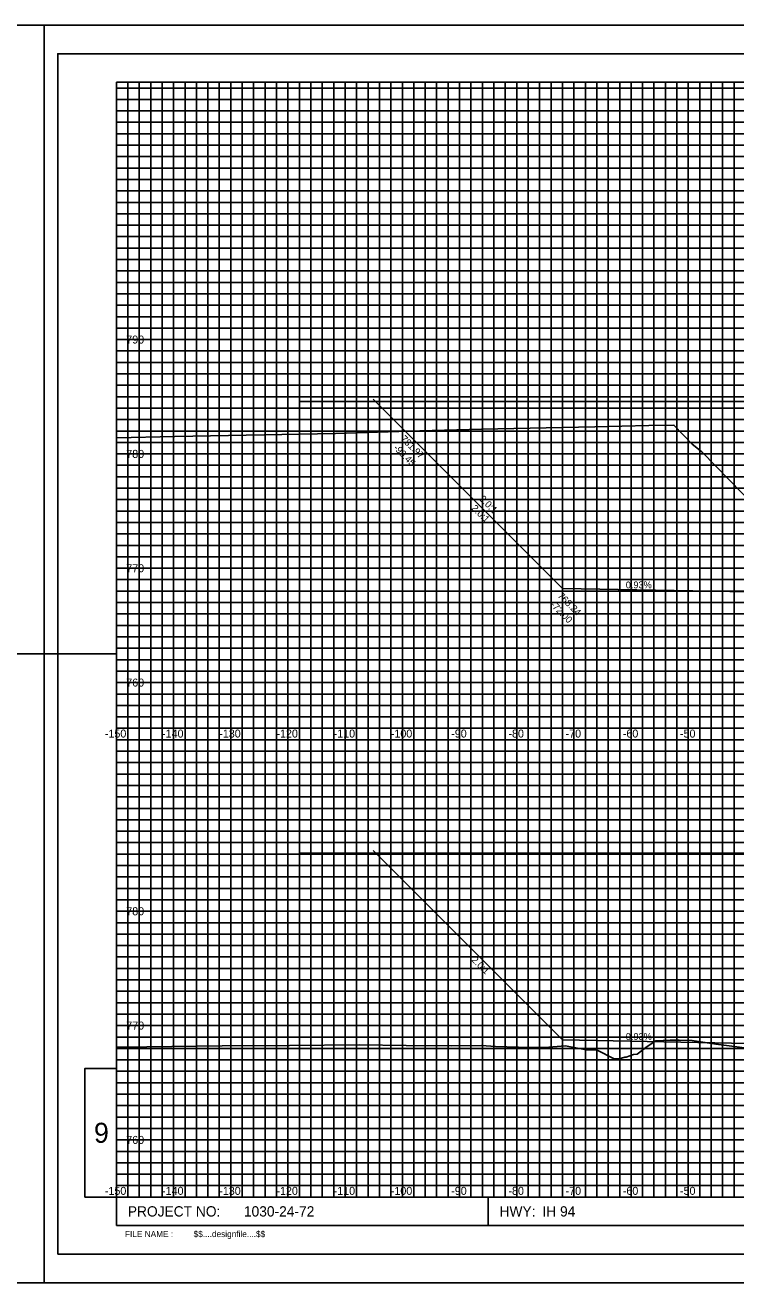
# Model space of a CAD drawing. Extents: x 578243 to 601557, y 174899 to 175559.
# Drawn here: x 600533.9 to 600658.2, y 175338.8 to 175558.8 of the extents above; entities that cross this region are included whole.
import ezdxf

# ---------------------------------------------------------------- set-up
doc = ezdxf.new("R2010")
doc.units = 0
for name, color, linetype in [('E_PROF_Grid', 7, 'Continuous'), ('E_PROF_GridMin', 7, 'Continuous'), ('P_CRDR_Label', 7, 'Continuous'), ('P_CRDR_Link', 7, 'Continuous'), ('P_E_XS_Ground', 7, 'Continuous'), ('P_RW_SlopeIntercepts', 7, 'Continuous'), ('P_XS_Text', 7, 'Continuous'), ('PLT_Sheet_Border', 7, 'Continuous'), ('PLT_Sheet_Info', 7, 'Continuous')]:
    doc.layers.add(name, color=color, linetype=linetype)

msp = doc.modelspace()

# ---------------------------------------------------------------- linework, layer by layer
at = {"layer": 'E_PROF_Grid'}
for p, q in [((600559.84, 175353.8), (600559.84, 175548.8)), ((600569.84, 175353.8), (600569.84, 175548.8)), ((600579.84, 175353.8), (600579.84, 175548.8)), ((600589.84, 175353.8), (600589.84, 175548.8)), ((600599.84, 175353.8), (600599.84, 175548.8)), ((600609.84, 175353.8), (600609.84, 175548.8)), ((600619.84, 175353.8), (600619.84, 175548.8)), ((600629.84, 175353.8), (600629.84, 175548.8)), ((600639.84, 175353.8), (600639.84, 175548.8)), ((600649.84, 175353.8), (600649.84, 175548.8)), ((600549.84, 175543.8), (600864.84, 175543.8)), ((600549.84, 175533.8), (600864.84, 175533.8)), ((600549.84, 175523.8), (600864.84, 175523.8)), ((600549.84, 175513.8), (600864.84, 175513.8)), ((600549.84, 175503.8), (600864.84, 175503.8)), ((600549.84, 175493.8), (600864.84, 175493.8)), ((600549.84, 175483.8), (600864.84, 175483.8)), ((600549.84, 175473.8), (600864.84, 175473.8)), ((600549.84, 175463.8), (600864.84, 175463.8)), ((600549.84, 175453.8), (600864.84, 175453.8)), ((600549.84, 175443.8), (600864.84, 175443.8)), ((600549.84, 175433.8), (600864.84, 175433.8)), ((600549.84, 175423.8), (600864.84, 175423.8)), ((600549.84, 175413.8), (600864.84, 175413.8)), ((600549.84, 175403.8), (600864.84, 175403.8)), ((600549.84, 175393.8), (600864.84, 175393.8)), ((600549.84, 175383.8), (600864.84, 175383.8)), ((600549.84, 175373.8), (600864.84, 175373.8)), ((600549.84, 175363.8), (600864.84, 175363.8))]:
    msp.add_line(p, q, dxfattribs=at)
at = {"layer": 'E_PROF_GridMin'}
for p, q in [((600549.84, 175547.8), (600864.84, 175547.8)), ((600551.84, 175353.8), (600551.84, 175548.8)), ((600553.84, 175353.8), (600553.84, 175548.8)), ((600555.84, 175353.8), (600555.84, 175548.8)), ((600557.84, 175353.8), (600557.84, 175548.8)), ((600561.84, 175353.8), (600561.84, 175548.8)), ((600563.84, 175353.8), (600563.84, 175548.8)), ((600565.84, 175353.8), (600565.84, 175548.8)), ((600567.84, 175353.8), (600567.84, 175548.8)), ((600571.84, 175353.8), (600571.84, 175548.8)), ((600573.84, 175353.8), (600573.84, 175548.8)), ((600575.84, 175353.8), (600575.84, 175548.8)), ((600577.84, 175353.8), (600577.84, 175548.8)), ((600581.84, 175353.8), (600581.84, 175548.8)), ((600583.84, 175353.8), (600583.84, 175548.8)), ((600585.84, 175353.8), (600585.84, 175548.8)), ((600587.84, 175353.8), (600587.84, 175548.8)), ((600591.84, 175353.8), (600591.84, 175548.8)), ((600593.84, 175353.8), (600593.84, 175548.8)), ((600595.84, 175353.8), (600595.84, 175548.8)), ((600597.84, 175353.8), (600597.84, 175548.8)), ((600601.84, 175353.8), (600601.84, 175548.8)), ((600603.84, 175353.8), (600603.84, 175548.8)), ((600605.84, 175353.8), (600605.84, 175548.8)), ((600607.84, 175353.8), (600607.84, 175548.8)), ((600611.84, 175353.8), (600611.84, 175548.8)), ((600613.84, 175353.8), (600613.84, 175548.8)), ((600615.84, 175353.8), (600615.84, 175548.8)), ((600617.84, 175353.8), (600617.84, 175548.8)), ((600621.84, 175353.8), (600621.84, 175548.8)), ((600623.84, 175353.8), (600623.84, 175548.8)), ((600625.84, 175353.8), (600625.84, 175548.8)), ((600627.84, 175353.8), (600627.84, 175548.8)), ((600631.84, 175353.8), (600631.84, 175548.8)), ((600633.84, 175353.8), (600633.84, 175548.8)), ((600635.84, 175353.8), (600635.84, 175548.8)), ((600637.84, 175353.8), (600637.84, 175548.8)), ((600641.84, 175353.8), (600641.84, 175548.8)), ((600643.84, 175353.8), (600643.84, 175548.8)), ((600645.84, 175353.8), (600645.84, 175548.8)), ((600647.84, 175353.8), (600647.84, 175548.8)), ((600651.84, 175353.8), (600651.84, 175548.8)), ((600653.84, 175353.8), (600653.84, 175548.8)), ((600655.84, 175353.8), (600655.84, 175548.8)), ((600657.84, 175353.8), (600657.84, 175548.8)), ((600549.84, 175545.8), (600864.84, 175545.8)), ((600549.84, 175541.8), (600864.84, 175541.8)), ((600549.84, 175539.8), (600864.84, 175539.8)), ((600549.84, 175537.8), (600864.84, 175537.8)), ((600549.84, 175535.8), (600864.84, 175535.8)), ((600549.84, 175531.8), (600864.84, 175531.8)), ((600549.84, 175529.8), (600864.84, 175529.8)), ((600549.84, 175527.8), (600864.84, 175527.8)), ((600549.84, 175525.8), (600864.84, 175525.8)), ((600549.84, 175521.8), (600864.84, 175521.8)), ((600549.84, 175519.8), (600864.84, 175519.8)), ((600549.84, 175517.8), (600864.84, 175517.8)), ((600549.84, 175515.8), (600864.84, 175515.8)), ((600549.84, 175511.8), (600864.84, 175511.8)), ((600549.84, 175509.8), (600864.84, 175509.8)), ((600549.84, 175507.8), (600864.84, 175507.8)), ((600549.84, 175505.8), (600864.84, 175505.8)), ((600549.84, 175501.8), (600864.84, 175501.8)), ((600549.84, 175499.8), (600864.84, 175499.8)), ((600549.84, 175497.8), (600864.84, 175497.8)), ((600549.84, 175495.8), (600864.84, 175495.8)), ((600549.84, 175491.8), (600864.84, 175491.8)), ((600549.84, 175489.8), (600864.84, 175489.8)), ((600549.84, 175487.8), (600864.84, 175487.8)), ((600549.84, 175485.8), (600864.84, 175485.8)), ((600549.84, 175481.8), (600864.84, 175481.8)), ((600549.84, 175479.8), (600864.84, 175479.8)), ((600549.84, 175477.8), (600864.84, 175477.8)), ((600549.84, 175475.8), (600864.84, 175475.8)), ((600549.84, 175471.8), (600864.84, 175471.8)), ((600549.84, 175469.8), (600864.84, 175469.8)), ((600549.84, 175467.8), (600864.84, 175467.8)), ((600549.84, 175465.8), (600864.84, 175465.8)), ((600549.84, 175461.8), (600864.84, 175461.8)), ((600549.84, 175459.8), (600864.84, 175459.8)), ((600549.84, 175457.8), (600864.84, 175457.8)), ((600549.84, 175455.8), (600864.84, 175455.8)), ((600549.84, 175451.8), (600864.84, 175451.8)), ((600549.84, 175449.8), (600864.84, 175449.8)), ((600549.84, 175447.8), (600864.84, 175447.8)), ((600549.84, 175445.8), (600864.84, 175445.8)), ((600549.84, 175441.8), (600864.84, 175441.8)), ((600549.84, 175439.8), (600864.84, 175439.8)), ((600549.84, 175437.8), (600864.84, 175437.8)), ((600549.84, 175435.8), (600864.84, 175435.8)), ((600549.84, 175431.8), (600864.84, 175431.8)), ((600549.84, 175429.8), (600864.84, 175429.8)), ((600549.84, 175427.8), (600864.84, 175427.8)), ((600549.84, 175425.8), (600864.84, 175425.8)), ((600549.84, 175421.8), (600864.84, 175421.8)), ((600549.84, 175419.8), (600864.84, 175419.8)), ((600549.84, 175417.8), (600864.84, 175417.8)), ((600549.84, 175415.8), (600864.84, 175415.8)), ((600549.84, 175411.8), (600864.84, 175411.8)), ((600549.84, 175409.8), (600864.84, 175409.8)), ((600549.84, 175407.8), (600864.84, 175407.8)), ((600549.84, 175405.8), (600864.84, 175405.8)), ((600549.84, 175401.8), (600864.84, 175401.8)), ((600549.84, 175399.8), (600864.84, 175399.8)), ((600549.84, 175397.8), (600864.84, 175397.8)), ((600549.84, 175395.8), (600864.84, 175395.8)), ((600549.84, 175391.8), (600864.84, 175391.8)), ((600549.84, 175389.8), (600864.84, 175389.8)), ((600549.84, 175387.8), (600864.84, 175387.8)), ((600549.84, 175385.8), (600864.84, 175385.8)), ((600549.84, 175381.8), (600864.84, 175381.8)), ((600549.84, 175379.8), (600864.84, 175379.8)), ((600549.84, 175377.8), (600864.84, 175377.8)), ((600549.84, 175375.8), (600864.84, 175375.8)), ((600549.84, 175371.8), (600864.84, 175371.8)), ((600549.84, 175369.8), (600864.84, 175369.8)), ((600549.84, 175367.8), (600864.84, 175367.8)), ((600549.84, 175365.8), (600864.84, 175365.8)), ((600549.84, 175361.8), (600864.84, 175361.8)), ((600549.84, 175359.8), (600864.84, 175359.8)), ((600549.84, 175357.8), (600864.84, 175357.8)), ((600549.84, 175355.8), (600864.84, 175355.8)), ((600537.19, 175338.8), (600537.19, 175348.8)), ((600527.19, 175338.8), (600537.19, 175338.8))]:
    msp.add_line(p, q, dxfattribs=at)
at = {"layer": 'P_CRDR_Link'}
for p, q in [((600594.72, 175493.4), (600627.84, 175460.28)), ((600594.72, 175414.4), (600627.84, 175381.28))]:
    msp.add_line(p, q, dxfattribs=at)
for points in [[(600627.84, 175460.28), (600600.39, 175487.73)], [(600627.84, 175460.28), (600600.39, 175487.73)], [(600660.34, 175459.68), (600627.84, 175460.28)], [(600660.34, 175459.68), (600627.84, 175460.28)], [(600660.34, 175380.68), (600627.84, 175381.28)], [(600660.34, 175380.68), (600627.84, 175381.28)]]:
    msp.add_lwpolyline(points, dxfattribs=at)
at = {"layer": 'P_E_XS_Ground'}
for points in [[(600549.84, 175486.63), (600560.06, 175486.86), (600588.16, 175487.38), (600602.92, 175487.81), (600613.68, 175488.14), (600633.52, 175488.55), (600642.91, 175488.77), (600647.33, 175488.85), (600650.52, 175485.53), (600652.19, 175484.15), (600652.24, 175484.1), (600677.78, 175457.95)], [(600549.84, 175380), (600555.15, 175380.1), (600568.32, 175380.26), (600580.11, 175380.31), (600592.31, 175380.45), (600600.52, 175380.33), (600608.44, 175380.28), (600613.66, 175380.31), (600616.11, 175380.16), (600622.16, 175379.94), (600624.72, 175379.97), (600628.37, 175380.23), (600631.98, 175379.56), (600633.88, 175379.48), (600636.9, 175377.97), (600637.23, 175377.96), (600637.73, 175377.98), (600638.74, 175378.28), (600638.96, 175378.3), (600640.24, 175378.73), (600640.9, 175378.81), (600642.67, 175380.12), (600644.15, 175381.12), (600646.68, 175381.25), (600648.27, 175381.25), (600650.5, 175381.18), (600654.68, 175380.57), (600657.92, 175380.12), (600661.4, 175379.69)]]:
    msp.add_lwpolyline(points, dxfattribs=at)
at = {"layer": 'P_RW_SlopeIntercepts'}
for p, q in [((600581.84, 175492.98), (600841.84, 175492.98)), ((600581.84, 175413.98), (600841.84, 175413.98))]:
    msp.add_line(p, q, dxfattribs=at)
at = {"layer": 'PLT_Sheet_Border'}
for points in [[(600197.19, 175338.8), (600537.19, 175338.8), (600537.19, 175558.8), (600197.19, 175558.8)], [(600537.19, 175338.8), (600877.19, 175338.8), (600877.19, 175558.8), (600537.19, 175558.8)], [(600539.59, 175343.8), (600870.59, 175343.8), (600870.59, 175553.8), (600539.59, 175553.8)]]:
    msp.add_lwpolyline(points, close=True, dxfattribs=at)
at = {"layer": 'PLT_Sheet_Info'}
for p, q in [((600527.19, 175558.8), (600537.19, 175558.8)), ((600537.19, 175548.8), (600537.19, 175558.8)), ((600537.19, 175548.8), (600537.19, 175558.8)), ((600537.19, 175558.8), (600547.19, 175558.8)), ((600549.84, 175548.8), (600864.84, 175548.8)), ((600549.84, 175348.8), (600549.84, 175548.8)), ((600537.19, 175443.8), (600537.19, 175453.8)), ((600537.19, 175443.8), (600537.19, 175453.8)), ((600537.19, 175448.8), (600524.84, 175448.8)), ((600537.19, 175448.8), (600549.84, 175448.8)), ((600549.84, 175353.8), (600864.84, 175353.8)), ((600614.84, 175348.8), (600614.84, 175353.8)), ((600537.19, 175338.8), (600537.19, 175348.8)), ((600549.84, 175348.8), (600864.84, 175348.8)), ((600537.19, 175338.8), (600547.19, 175338.8))]:
    msp.add_line(p, q, dxfattribs=at)
msp.add_lwpolyline([(600549.84, 175376.3), (600544.34, 175376.3), (600544.34, 175353.8), (600549.84, 175353.8)], close=True, dxfattribs=at)

# ---------------------------------------------------------------- texts
at = {"layer": 'P_CRDR_Label'}
for s, rotation, p in [('781.97', 315, (600599.46, 175486.32)), ('781.97', 315, (600599.46, 175486.32)), ('-99.45', 315, (600598.2, 175484.74)), ('-99.45', 315, (600598.2, 175484.74)), ('2.0:1', 315, (600613.21, 175475.82)), ('2.0:1', 315.8532, (600611.83, 175474.17)), ('0.93%', 0.4313, (600638.91, 175460.27)), ('768.24', 315, (600626.91, 175458.87)), ('-72.00', 315, (600625.64, 175457.3)), ('2.0:1', 315.8532, (600611.83, 175395.17)), ('0.93%', 0.4313, (600638.91, 175381.27))]:
    msp.add_text(s, height=1.2, rotation=rotation, dxfattribs=at).set_placement(p)
at = {"layer": 'P_XS_Text'}
for s, p in [('790', (600551.57, 175503.1)), ('780', (600551.57, 175483.1)), ('770', (600551.57, 175463.1)), ('760', (600551.57, 175443.1)), ('-150', (600547.83, 175434.18)), ('-140', (600557.83, 175434.18)), ('-130', (600567.83, 175434.18)), ('-120', (600577.83, 175434.18)), ('-110', (600587.83, 175434.18)), ('-100', (600597.83, 175434.18)), ('-90', (600608.39, 175434.18)), ('-80', (600618.39, 175434.18)), ('-70', (600628.39, 175434.18)), ('-60', (600638.39, 175434.18)), ('-50', (600648.39, 175434.18)), ('780', (600551.57, 175403.1)), ('770', (600551.57, 175383.1)), ('760', (600551.57, 175363.1)), ('-150', (600547.83, 175354.19)), ('-140', (600557.83, 175354.19)), ('-130', (600567.83, 175354.19)), ('-120', (600577.83, 175354.19)), ('-110', (600587.83, 175354.19)), ('-100', (600597.83, 175354.19)), ('-90', (600608.39, 175354.19)), ('-80', (600618.39, 175354.19)), ('-70', (600628.39, 175354.19)), ('-60', (600638.39, 175354.19)), ('-50', (600648.39, 175354.19))]:
    msp.add_text(s, height=1.4, rotation=360, dxfattribs=at).set_placement(p)
at = {"layer": 'PLT_Sheet_Info'}
for s, height, p in [('9', 3.5, (600545.92, 175363.3)), ('PROJECT NO:', 1.8, (600551.84, 175350.4)), ('1030-24-72             ', 1.8, (600572.14, 175350.4)), ('HWY:', 1.8, (600616.84, 175350.4)), ('IH 94               ', 1.8, (600624.34, 175350.4)), ('FILE NAME :', 1.08, (600551.34, 175346.8))]:
    msp.add_text(s, height=height, dxfattribs=at).set_placement(p)
msp.add_text('$$....designfile....$$', height=1.08, rotation=360, dxfattribs=at).set_placement((600563.34, 175346.8))

doc.saveas('drawing.dxf')
